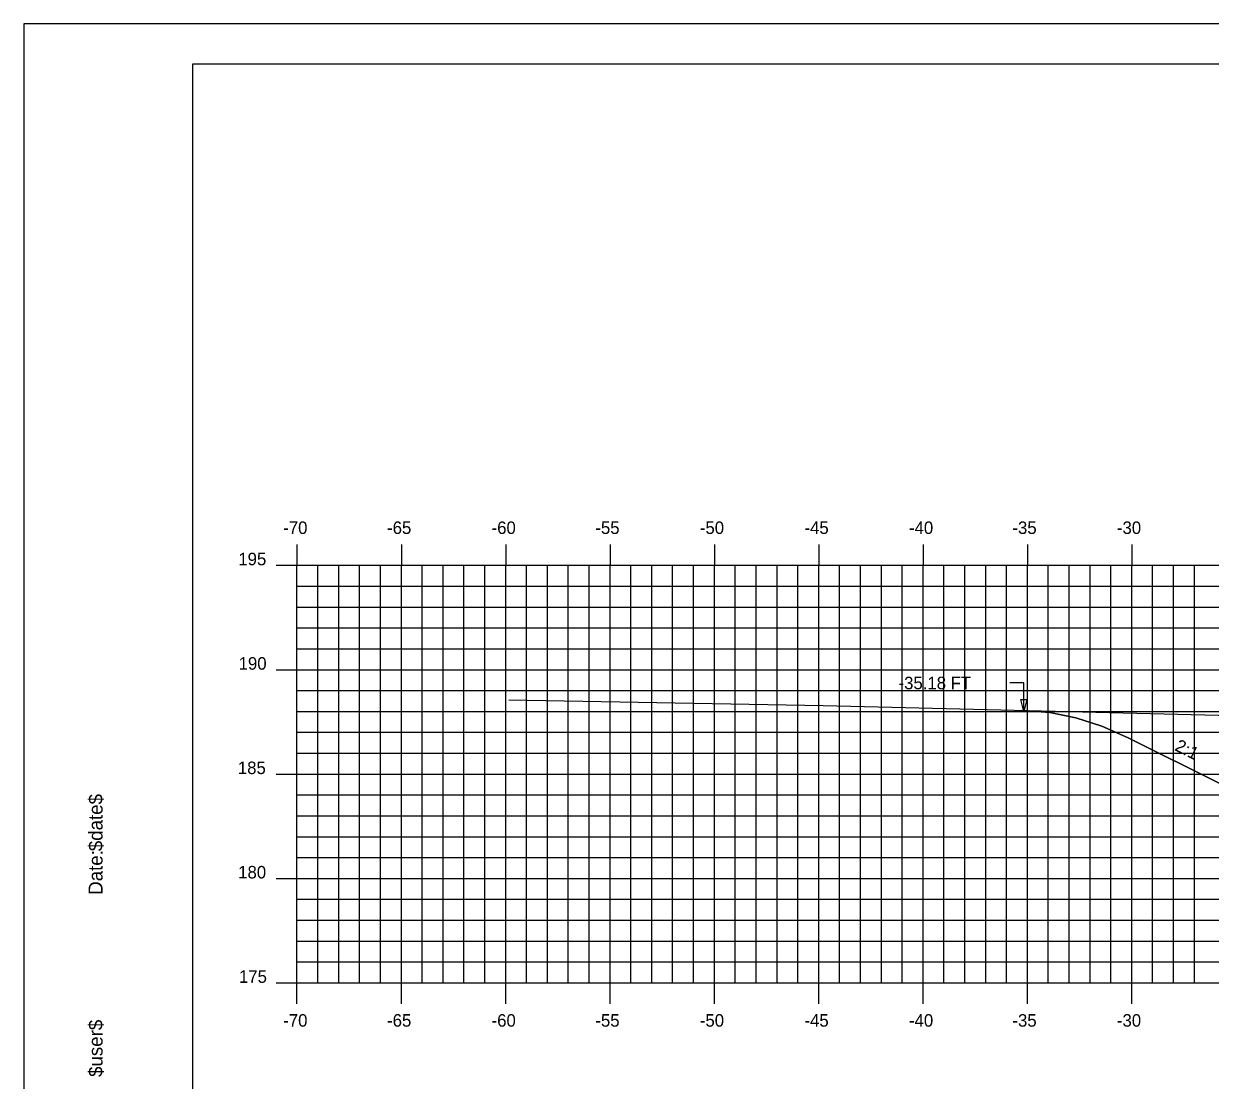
# Model space of a CAD drawing. Extents: x 1139428 to 1139598, y 608981 to 609091.
# Drawn here: x 1139428.4 to 1139485.2, y 609040.7 to 609091.3 of the extents above; entities that cross this region are included whole.
import ezdxf

# ---------------------------------------------------------------- set-up
doc = ezdxf.new("R2010")
doc.units = 0
for name, color, linetype in [('ANNOTATION', 7, 'Continuous'), ('BORDER', 7, 'Continuous'), ('D_Roadway_SlopeLines', 7, 'Continuous'), ('D_Text_Standard', 7, 'Continuous'), ('H_V ANNOTATION', 7, 'Continuous'), ('MAJOR', 7, 'Continuous'), ('MINOR', 7, 'Continuous'), ('PLOT BOUNDARY', 7, 'Continuous'), ('S_Roadway_Centerline', 7, 'Continuous')]:
    doc.layers.add(name, color=color, linetype=linetype)

msp = doc.modelspace()

# ---------------------------------------------------------------- linework, layer by layer
msp.add_lwpolyline([(1139476.282, 609058.385), (1139477.532, 609058.28), (1139478.782, 609058.027), (1139480.032, 609057.625), (1139481.282, 609057.074), (1139485.737, 609054.846), (1139488.737, 609055.846), (1139496.461, 609058.421), (1139496.462, 609058.421), (1139500.462, 609058.581), (1139511.462, 609058.801), (1139522.462, 609058.581), (1139526.462, 609058.421)])
at = {"layer": 'BORDER'}
msp.add_lwpolyline([(1139436.462, 608984.335), (1139596.462, 608984.335), (1139596.462, 609089.335), (1139436.462, 609089.335)], close=True, dxfattribs=at)
at = {"layer": 'D_Roadway_SlopeLines'}
msp.add_lwpolyline([(1139485.737, 609054.846), (1139481.282, 609057.074), (1139480.032, 609057.625), (1139478.782, 609058.027), (1139477.532, 609058.28), (1139476.282, 609058.385)], dxfattribs=at)
at = {"layer": 'D_Text_Standard'}
msp.add_lwpolyline([(1139476.282, 609058.324), (1139476.292, 609059.698), (1139475.612, 609059.698)], dxfattribs=at)
msp.add_lwpolyline([(1139476.282, 609058.324), (1139476.141, 609058.907), (1139476.432, 609058.905)], close=True, dxfattribs=at)
at = {"layer": 'MAJOR'}
for p, q in [((1139441.462, 609066.337), (1139441.462, 609065.335)), ((1139446.462, 609066.337), (1139446.462, 609065.335)), ((1139451.462, 609066.337), (1139451.462, 609065.335)), ((1139456.462, 609066.337), (1139456.462, 609065.335)), ((1139461.462, 609066.337), (1139461.462, 609065.335)), ((1139466.462, 609066.337), (1139466.462, 609065.335)), ((1139471.462, 609066.337), (1139471.462, 609065.335)), ((1139476.462, 609066.337), (1139476.462, 609065.335)), ((1139481.462, 609066.337), (1139481.462, 609065.335)), ((1139440.46, 609065.335), (1139441.462, 609065.335)), ((1139441.462, 609065.335), (1139581.462, 609065.335)), ((1139441.462, 609045.335), (1139441.462, 609065.335)), ((1139441.462, 609045.335), (1139441.462, 609065.335)), ((1139441.462, 609065.335), (1139581.462, 609065.335)), ((1139446.462, 609045.335), (1139446.462, 609065.335)), ((1139451.462, 609045.335), (1139451.462, 609065.335)), ((1139456.462, 609045.335), (1139456.462, 609065.335)), ((1139461.462, 609045.335), (1139461.462, 609065.335)), ((1139466.462, 609045.335), (1139466.462, 609065.335)), ((1139471.462, 609045.335), (1139471.462, 609065.335)), ((1139476.462, 609045.335), (1139476.462, 609065.335)), ((1139481.462, 609045.335), (1139481.462, 609065.335)), ((1139440.46, 609060.335), (1139441.462, 609060.335)), ((1139441.462, 609060.335), (1139581.462, 609060.335)), ((1139440.46, 609055.335), (1139441.462, 609055.335)), ((1139441.462, 609055.335), (1139581.462, 609055.335)), ((1139440.46, 609050.335), (1139441.462, 609050.335)), ((1139441.462, 609050.335), (1139581.462, 609050.335)), ((1139440.46, 609045.335), (1139441.462, 609045.335)), ((1139441.462, 609045.335), (1139581.462, 609045.335)), ((1139441.462, 609045.335), (1139581.462, 609045.335)), ((1139441.462, 609044.333), (1139441.462, 609045.335)), ((1139446.462, 609044.333), (1139446.462, 609045.335)), ((1139451.462, 609044.333), (1139451.462, 609045.335)), ((1139456.462, 609044.333), (1139456.462, 609045.335)), ((1139461.462, 609044.333), (1139461.462, 609045.335)), ((1139466.462, 609044.333), (1139466.462, 609045.335)), ((1139471.462, 609044.333), (1139471.462, 609045.335)), ((1139476.462, 609044.333), (1139476.462, 609045.335)), ((1139481.462, 609044.333), (1139481.462, 609045.335))]:
    msp.add_line(p, q, dxfattribs=at)
at = {"layer": 'MINOR'}
for p, q in [((1139442.462, 609045.335), (1139442.462, 609065.335)), ((1139443.462, 609045.335), (1139443.462, 609065.335)), ((1139444.462, 609045.335), (1139444.462, 609065.335)), ((1139445.462, 609045.335), (1139445.462, 609065.335)), ((1139447.462, 609045.335), (1139447.462, 609065.335)), ((1139448.462, 609045.335), (1139448.462, 609065.335)), ((1139449.462, 609045.335), (1139449.462, 609065.335)), ((1139450.462, 609045.335), (1139450.462, 609065.335)), ((1139452.462, 609045.335), (1139452.462, 609065.335)), ((1139453.462, 609045.335), (1139453.462, 609065.335)), ((1139454.462, 609045.335), (1139454.462, 609065.335)), ((1139455.462, 609045.335), (1139455.462, 609065.335)), ((1139457.462, 609045.335), (1139457.462, 609065.335)), ((1139458.462, 609045.335), (1139458.462, 609065.335)), ((1139459.462, 609045.335), (1139459.462, 609065.335)), ((1139460.462, 609045.335), (1139460.462, 609065.335)), ((1139462.462, 609045.335), (1139462.462, 609065.335)), ((1139463.462, 609045.335), (1139463.462, 609065.335)), ((1139464.462, 609045.335), (1139464.462, 609065.335)), ((1139465.462, 609045.335), (1139465.462, 609065.335)), ((1139467.462, 609045.335), (1139467.462, 609065.335)), ((1139468.462, 609045.335), (1139468.462, 609065.335)), ((1139469.462, 609045.335), (1139469.462, 609065.335)), ((1139470.462, 609045.335), (1139470.462, 609065.335)), ((1139472.462, 609045.335), (1139472.462, 609065.335)), ((1139473.462, 609045.335), (1139473.462, 609065.335)), ((1139474.462, 609045.335), (1139474.462, 609065.335)), ((1139475.462, 609045.335), (1139475.462, 609065.335)), ((1139477.462, 609045.335), (1139477.462, 609065.335)), ((1139478.462, 609045.335), (1139478.462, 609065.335)), ((1139479.462, 609045.335), (1139479.462, 609065.335)), ((1139480.462, 609045.335), (1139480.462, 609065.335)), ((1139482.462, 609045.335), (1139482.462, 609065.335)), ((1139483.462, 609045.335), (1139483.462, 609065.335)), ((1139484.462, 609045.335), (1139484.462, 609065.335)), ((1139441.462, 609064.335), (1139581.462, 609064.335)), ((1139441.462, 609064.335), (1139442.464, 609064.335)), ((1139441.462, 609063.335), (1139581.462, 609063.335)), ((1139441.462, 609063.335), (1139442.464, 609063.335)), ((1139441.462, 609062.335), (1139581.462, 609062.335)), ((1139441.462, 609062.335), (1139442.464, 609062.335)), ((1139441.462, 609061.335), (1139581.462, 609061.335)), ((1139441.462, 609061.335), (1139442.464, 609061.335)), ((1139441.462, 609059.335), (1139581.462, 609059.335)), ((1139441.462, 609059.335), (1139442.464, 609059.335)), ((1139441.462, 609058.335), (1139581.462, 609058.335)), ((1139441.462, 609058.335), (1139442.464, 609058.335)), ((1139441.462, 609057.335), (1139581.462, 609057.335)), ((1139441.462, 609057.335), (1139442.464, 609057.335)), ((1139441.462, 609056.335), (1139581.462, 609056.335)), ((1139441.462, 609056.335), (1139442.464, 609056.335)), ((1139441.462, 609054.335), (1139581.462, 609054.335)), ((1139441.462, 609054.335), (1139442.464, 609054.335)), ((1139441.462, 609053.335), (1139581.462, 609053.335)), ((1139441.462, 609053.335), (1139442.464, 609053.335)), ((1139441.462, 609052.335), (1139581.462, 609052.335)), ((1139441.462, 609052.335), (1139442.464, 609052.335)), ((1139441.462, 609051.335), (1139581.462, 609051.335)), ((1139441.462, 609051.335), (1139442.464, 609051.335)), ((1139441.462, 609049.335), (1139581.462, 609049.335)), ((1139441.462, 609049.335), (1139442.464, 609049.335)), ((1139441.462, 609048.335), (1139581.462, 609048.335)), ((1139441.462, 609048.335), (1139442.464, 609048.335)), ((1139441.462, 609047.335), (1139581.462, 609047.335)), ((1139441.462, 609047.335), (1139442.464, 609047.335)), ((1139441.462, 609046.335), (1139581.462, 609046.335)), ((1139441.462, 609046.335), (1139442.464, 609046.335))]:
    msp.add_line(p, q, dxfattribs=at)
at = {"layer": 'PLOT BOUNDARY'}
msp.add_lwpolyline([(1139428.369, 608981.276), (1139598.369, 608981.276), (1139598.369, 609091.276), (1139428.369, 609091.276)], close=True, dxfattribs=at)
at = {"layer": 'S_Roadway_Centerline'}
msp.add_lwpolyline([(1139451.612, 609058.889), (1139466.676, 609058.616), (1139468.652, 609058.571), (1139486.265, 609058.142)], dxfattribs=at)

# ---------------------------------------------------------------- texts
at = {"layer": 'ANNOTATION'}
msp.add_text('2:1', height=0.6, rotation=333.4349, dxfattribs=at).set_placement((1139483.477, 609056.495))
at = {"layer": 'BORDER'}
for s, p in [('$date$', (1139432.147, 609051.64)), ('Date:', (1139432.147, 609049.552)), ('$user$', (1139432.147, 609040.827))]:
    msp.add_text(s, height=0.6696, rotation=90, dxfattribs=at).set_placement(p)
at = {"layer": 'D_Text_Standard'}
msp.add_text('-35.18 FT', height=0.6, dxfattribs=at).set_placement((1139470.286, 609059.398))
at = {"layer": 'H_V ANNOTATION'}
for s, p in [('-70', (1139440.803, 609066.835)), ('-65', (1139445.779, 609066.835)), ('-60', (1139450.787, 609066.835)), ('-55', (1139455.758, 609066.835)), ('-50', (1139460.766, 609066.835)), ('-45', (1139465.779, 609066.835)), ('-40', (1139470.787, 609066.835)), ('-35', (1139475.742, 609066.835)), ('-30', (1139480.75, 609066.835)), ('195', (1139438.651, 609065.335)), ('190', (1139438.667, 609060.335)), ('185', (1139438.629, 609055.335)), ('180', (1139438.645, 609050.335)), ('175', (1139438.682, 609045.335)), ('-70', (1139440.803, 609043.235)), ('-65', (1139445.779, 609043.235)), ('-60', (1139450.787, 609043.235)), ('-55', (1139455.758, 609043.235)), ('-50', (1139460.766, 609043.235)), ('-45', (1139465.779, 609043.235)), ('-40', (1139470.787, 609043.235)), ('-35', (1139475.742, 609043.235)), ('-30', (1139480.75, 609043.235))]:
    msp.add_text(s, height=0.6, dxfattribs=at).set_placement(p)
at = {"layer": 'MAJOR'}
msp.add_text('-', height=0.006, dxfattribs=at).set_placement((1139441.457, 609045.335))

doc.saveas('drawing.dxf')
